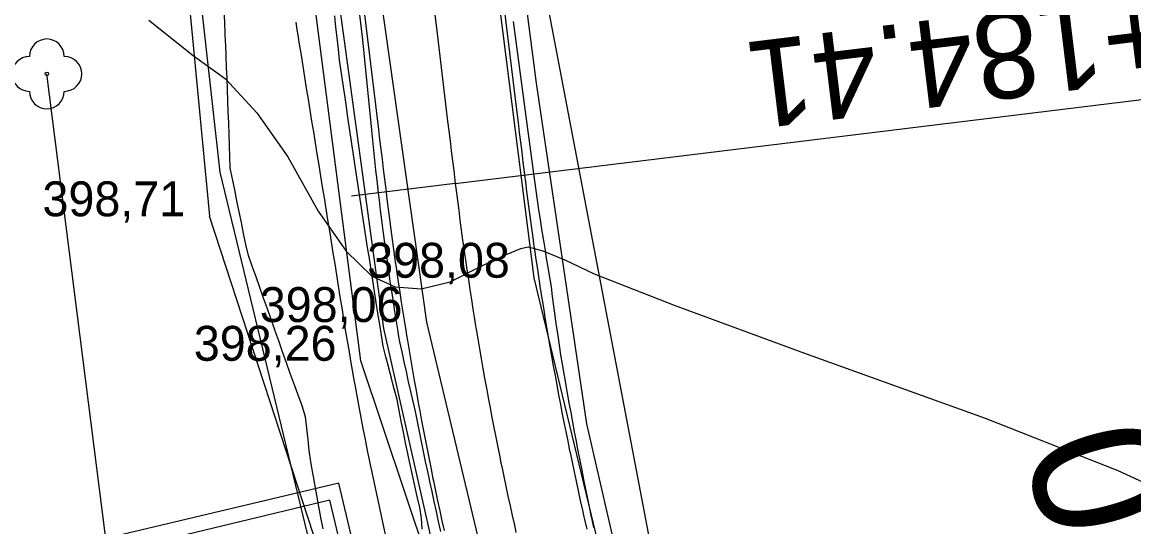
# Model space of a CAD drawing. Extents: x -574342 to -507939, y -1144044 to -1123894.
# Drawn here: x -508553.2 to -508521.32, y -1143234.06 to -1143219.6 of the extents above; entities that cross this region are included whole.
import ezdxf

# ---------------------------------------------------------------- set-up
doc = ezdxf.new("R2010")
doc.units = 0
for name, color, linetype in [('01_PARCELY_NAVRH_PC', 7, 'Continuous'), ('01_PARCELY_NAVRH_VHO', 7, 'Continuous'), ('01_PARCELY_NAVRH_ŽP', 7, 'Continuous'), ('1000', 7, 'Continuous'), ('18', 7, 'Continuous'), ('21', 7, 'Continuous'), ('23', 7, 'Continuous'), ('37', 7, 'Continuous'), ('42', 7, 'Continuous'), ('54', 7, 'Continuous'), ('55', 7, 'Continuous'), ('62', 7, 'Continuous'), ('Level 255', 7, 'Continuous'), ('SO 101_popis oblouku', 7, 'Continuous'), ('VRST VEDL', 7, 'Continuous')]:
    doc.layers.add(name, color=color, linetype=linetype)

msp = doc.modelspace()

# ---------------------------------------------------------------- linework, layer by layer
msp.add_lwpolyline([(-508538.692, -1143255.691), (-508544.119, -1143232.805), (-508565.304, -1143237.829), (-508559.878, -1143260.714)], close=True)
at = {"layer": '01_PARCELY_NAVRH_PC'}
msp.add_lwpolyline([(-508524.61, -1143277.77), (-508531.94, -1143260.32), (-508534.5, -1143254.93), (-508536.24, -1143250.83), (-508539.07, -1143243.44), (-508539.77, -1143241.25), (-508540.55, -1143238.43), (-508542.83, -1143228.38), (-508544.32, -1143217.47), (-508545.45, -1143205.07), (-508545.52, -1143198.58), (-508545.24, -1143191.32), (-508544.97, -1143188.3), (-508544.25, -1143181.83), (-508541.94, -1143173.53), (-508537.18, -1143176.51), (-508538.65, -1143182.46), (-508540.32, -1143193.28), (-508540.02, -1143209.35), (-508538.46, -1143221.35), (-508537.02, -1143231.11), (-508535.34, -1143238.37), (-508531.16, -1143250.06), (-508524.26, -1143263.08)], dxfattribs=at)
msp.add_lwpolyline([(-508524.61, -1143277.77), (-508531.94, -1143260.32), (-508534.5, -1143254.93), (-508536.24, -1143250.83), (-508539.07, -1143243.44), (-508539.77, -1143241.25), (-508540.55, -1143238.43), (-508542.83, -1143228.38), (-508544.32, -1143217.47), (-508545.45, -1143205.07), (-508545.52, -1143198.58), (-508545.24, -1143191.32), (-508544.97, -1143188.3), (-508544.25, -1143181.83), (-508541.94, -1143173.53), (-508537.18, -1143176.51), (-508538.65, -1143182.46), (-508540.32, -1143193.28), (-508540.02, -1143209.35), (-508538.46, -1143221.35), (-508537.02, -1143231.11), (-508535.34, -1143238.37), (-508531.16, -1143250.06), (-508524.26, -1143263.08)], dxfattribs=at)
at = {"layer": '01_PARCELY_NAVRH_VHO'}
msp.add_lwpolyline([(-508536.24, -1143250.83), (-508539.07, -1143243.44), (-508539.77, -1143241.25), (-508540.55, -1143238.43), (-508542.83, -1143228.38), (-508544.32, -1143217.47), (-508545.45, -1143205.07), (-508545.52, -1143198.58), (-508545.24, -1143191.32), (-508544.97, -1143188.3), (-508544.25, -1143181.83), (-508551.68, -1143170.14), (-508558.5, -1143170.32), (-508555.03, -1143173.64), (-508548.66, -1143186.8), (-508549.63, -1143198.15), (-508549.79, -1143203.71), (-508547.53, -1143223.9), (-508542.99, -1143242.68), (-508538.24, -1143253.15)], close=True, dxfattribs=at)
at = {"layer": '01_PARCELY_NAVRH_ŽP'}
msp.add_lwpolyline([(-508555.03, -1143173.64), (-508548.66, -1143186.8), (-508549.63, -1143198.15), (-508549.79, -1143203.71), (-508547.53, -1143223.9), (-508542.99, -1143242.68), (-508538.24, -1143253.15), (-508539.95, -1143255.3), (-508547.25, -1143258.62), (-508651.11, -1143191.46), (-508662.59, -1143152.85), (-508637.59, -1143153.08), (-508621.09, -1143158.13), (-508610.87, -1143164.96), (-508585.59, -1143176.01), (-508569.25, -1143175.97)], close=True, dxfattribs=at)
at = {"layer": '1000'}
for points in [[(-508540.667, -1143208.641), (-508539.328, -1143219.604), (-508539.013, -1143222.188), (-508538.978, -1143222.472), (-508538.943, -1143222.756), (-508538.908, -1143223.041), (-508538.874, -1143223.325), (-508538.839, -1143223.61), (-508538.804, -1143223.894), (-508538.794, -1143223.978), (-508538.77, -1143224.174), (-508538.735, -1143224.453), (-508538.699, -1143224.731), (-508538.662, -1143225.01), (-508538.625, -1143225.288), (-508538.587, -1143225.566), (-508538.548, -1143225.844), (-508538.533, -1143225.95), (-508538.508, -1143226.122), (-508538.467, -1143226.4), (-508538.426, -1143226.678), (-508538.384, -1143226.955), (-508538.341, -1143227.233), (-508538.297, -1143227.51), (-508538.253, -1143227.787), (-508538.231, -1143227.917), (-508538.207, -1143228.064), (-508538.161, -1143228.341), (-508538.114, -1143228.618), (-508538.066, -1143228.895), (-508538.018, -1143229.171), (-508537.969, -1143229.448), (-508537.918, -1143229.724), (-508537.89, -1143229.877), (-508537.868, -1143230), (-508537.816, -1143230.276), (-508537.763, -1143230.552), (-508537.71, -1143230.828), (-508537.656, -1143231.103), (-508537.601, -1143231.379), (-508537.546, -1143231.654), (-508537.51, -1143231.83), (-508537.489, -1143231.929), (-508537.432, -1143232.204), (-508537.374, -1143232.478), (-508537.315, -1143232.753), (-508537.256, -1143233.027), (-508537.195, -1143233.302), (-508537.134, -1143233.576), (-508537.089, -1143233.774), (-508537.072, -1143233.85), (-508537.009, -1143234.123)], [(-508544.763, -1143209.141), (-508543.435, -1143220.105), (-508543.18, -1143222.696), (-508543.152, -1143222.982), (-508543.124, -1143223.267), (-508543.096, -1143223.552), (-508543.067, -1143223.837), (-508543.033, -1143224.122), (-508543, -1143224.406), (-508542.99, -1143224.49), (-508542.965, -1143224.695), (-508542.929, -1143224.986), (-508542.892, -1143225.276), (-508542.854, -1143225.567), (-508542.816, -1143225.857), (-508542.776, -1143226.147), (-508542.735, -1143226.437), (-508542.72, -1143226.548), (-508542.694, -1143226.727), (-508542.652, -1143227.017), (-508542.609, -1143227.307), (-508542.565, -1143227.597), (-508542.52, -1143227.886), (-508542.474, -1143228.175), (-508542.428, -1143228.464), (-508542.406, -1143228.6), (-508542.376, -1143228.753), (-508542.315, -1143229.04), (-508542.254, -1143229.326), (-508542.191, -1143229.612), (-508542.128, -1143229.899), (-508542.063, -1143230.184), (-508541.998, -1143230.47), (-508541.962, -1143230.628), (-508541.932, -1143230.755), (-508541.869, -1143231.041), (-508541.812, -1143231.328), (-508541.755, -1143231.615), (-508541.697, -1143231.902), (-508541.639, -1143232.189), (-508541.579, -1143232.475), (-508541.54, -1143232.658), (-508541.518, -1143232.761), (-508541.456, -1143233.047), (-508541.394, -1143233.333), (-508541.33, -1143233.619), (-508541.266, -1143233.904), (-508541.2, -1143234.189)], [(-508544.637, -1143209.126), (-508543.299, -1143220.089), (-508542.983, -1143222.672), (-508542.948, -1143222.957), (-508542.914, -1143223.241), (-508542.879, -1143223.526), (-508542.844, -1143223.81), (-508542.809, -1143224.094), (-508542.775, -1143224.379), (-508542.764, -1143224.463), (-508542.739, -1143224.667), (-508542.703, -1143224.957), (-508542.666, -1143225.247), (-508542.627, -1143225.537), (-508542.589, -1143225.826), (-508542.549, -1143226.116), (-508542.508, -1143226.405), (-508542.492, -1143226.516), (-508542.467, -1143226.695), (-508542.425, -1143226.984), (-508542.381, -1143227.273), (-508542.338, -1143227.562), (-508542.293, -1143227.851), (-508542.247, -1143228.139), (-508542.201, -1143228.428), (-508542.179, -1143228.563), (-508542.154, -1143228.716), (-508542.106, -1143229.004), (-508542.057, -1143229.292), (-508542.007, -1143229.58), (-508541.957, -1143229.868), (-508541.905, -1143230.156), (-508541.853, -1143230.444), (-508541.824, -1143230.603), (-508541.8, -1143230.731), (-508541.746, -1143231.018), (-508541.692, -1143231.305), (-508541.636, -1143231.592), (-508541.58, -1143231.879), (-508541.523, -1143232.166), (-508541.465, -1143232.452), (-508541.428, -1143232.635), (-508541.406, -1143232.738), (-508541.347, -1143233.024), (-508541.286, -1143233.31), (-508541.225, -1143233.596), (-508541.163, -1143233.882), (-508541.1, -1143234.167)], [(-508544.57, -1143234.112), (-508544.631, -1143233.793), (-508544.691, -1143233.474), (-508544.749, -1143233.155), (-508544.807, -1143232.835), (-508544.845, -1143232.616), (-508544.863, -1143232.516), (-508544.918, -1143232.196), (-508544.966, -1143231.875), (-508545.002, -1143231.551), (-508545.036, -1143231.228), (-508545.07, -1143230.904), (-508545.167, -1143230.592), (-508545.208, -1143230.485), (-508545.283, -1143230.284), (-508545.392, -1143229.99), (-508545.398, -1143229.975), (-508545.511, -1143229.665), (-508545.623, -1143229.355), (-508545.734, -1143229.044), (-508545.843, -1143228.732), (-508545.952, -1143228.42), (-508545.953, -1143228.416), (-508546.059, -1143228.114), (-508546.167, -1143227.808), (-508546.275, -1143227.502), (-508546.384, -1143227.197), (-508546.493, -1143226.891), (-508546.602, -1143226.585), (-508546.711, -1143226.28), (-508546.786, -1143225.969), (-508546.848, -1143225.655), (-508546.911, -1143225.342), (-508546.975, -1143225.029), (-508547.039, -1143224.716), (-508547.103, -1143224.403), (-508547.167, -1143224.091), (-508547.232, -1143223.778), (-508547.246, -1143223.457), (-508547.256, -1143223.135), (-508547.266, -1143222.814), (-508547.277, -1143222.492), (-508547.289, -1143222.171), (-508547.3, -1143221.849), (-508547.312, -1143221.528), (-508547.324, -1143221.207), (-508547.336, -1143220.885), (-508547.349, -1143220.564), (-508547.362, -1143220.243), (-508547.365, -1143220.151), (-508547.375, -1143219.922), (-508547.388, -1143219.601), (-508547.402, -1143219.28)], [(-508541.727, -1143234.125), (-508541.75, -1143233.813), (-508541.8, -1143233.501), (-508541.87, -1143233.193), (-508541.939, -1143232.885), (-508542.007, -1143232.577), (-508542.074, -1143232.268), (-508542.119, -1143232.057), (-508542.139, -1143231.96), (-508542.204, -1143231.651), (-508542.267, -1143231.342), (-508542.328, -1143231.032), (-508542.389, -1143230.722), (-508542.448, -1143230.412), (-508542.528, -1143230.106), (-508542.556, -1143229.999), (-508542.609, -1143229.8), (-508542.686, -1143229.508), (-508542.689, -1143229.494), (-508542.769, -1143229.187), (-508542.844, -1143228.879), (-508542.896, -1143228.567), (-508542.946, -1143228.256), (-508542.996, -1143227.944), (-508542.996, -1143227.939), (-508543.045, -1143227.628), (-508543.095, -1143227.313), (-508543.144, -1143226.998), (-508543.194, -1143226.683), (-508543.243, -1143226.367), (-508543.292, -1143226.052), (-508543.341, -1143225.736), (-508543.389, -1143225.421), (-508543.438, -1143225.106), (-508543.486, -1143224.79), (-508543.534, -1143224.475), (-508543.582, -1143224.159), (-508543.629, -1143223.844), (-508543.677, -1143223.528), (-508543.724, -1143223.212), (-508543.771, -1143222.897), (-508543.818, -1143222.581), (-508543.865, -1143222.265), (-508543.912, -1143221.95), (-508543.958, -1143221.634), (-508544.004, -1143221.318), (-508544.05, -1143221.002), (-508544.095, -1143220.686), (-508544.13, -1143220.369), (-508544.165, -1143220.051), (-508544.2, -1143219.733), (-508544.21, -1143219.642), (-508544.235, -1143219.416)], [(-508539.124, -1143219.579), (-508538.777, -1143222.159), (-508538.739, -1143222.443), (-508538.701, -1143222.727), (-508538.663, -1143223.011), (-508538.625, -1143223.295), (-508538.587, -1143223.579), (-508538.55, -1143223.863), (-508538.538, -1143223.947), (-508538.512, -1143224.142), (-508538.474, -1143224.42), (-508538.435, -1143224.697), (-508538.393, -1143224.974), (-508538.35, -1143225.251), (-508538.306, -1143225.527), (-508538.261, -1143225.804), (-508538.243, -1143225.909), (-508538.215, -1143226.08), (-508538.169, -1143226.356), (-508538.121, -1143226.632), (-508538.073, -1143226.908), (-508538.034, -1143227.185), (-508537.998, -1143227.462), (-508537.96, -1143227.74), (-508537.942, -1143227.87), (-508537.922, -1143228.017), (-508537.883, -1143228.295), (-508537.843, -1143228.572), (-508537.802, -1143228.849), (-508537.76, -1143229.126), (-508537.713, -1143229.402), (-508537.666, -1143229.678), (-508537.639, -1143229.831), (-508537.617, -1143229.954), (-508537.569, -1143230.23), (-508537.519, -1143230.505), (-508537.469, -1143230.781), (-508537.418, -1143231.056), (-508537.366, -1143231.332), (-508537.314, -1143231.607), (-508537.28, -1143231.783), (-508537.261, -1143231.882), (-508537.208, -1143232.157), (-508537.154, -1143232.432), (-508537.099, -1143232.706), (-508537.043, -1143232.981), (-508536.987, -1143233.255), (-508536.93, -1143233.53), (-508536.888, -1143233.729), (-508536.872, -1143233.804), (-508536.814, -1143234.078)]]:
    msp.add_lwpolyline(points, dxfattribs=at)
at = {"layer": '21'}
for points in [[(-508542.652, -1143208.884), (-508541.313, -1143219.846), (-508540.998, -1143222.43), (-508540.963, -1143222.714), (-508540.928, -1143222.999), (-508540.894, -1143223.283), (-508540.859, -1143223.568), (-508540.824, -1143223.852), (-508540.789, -1143224.136), (-508540.779, -1143224.22), (-508540.754, -1143224.421), (-508540.719, -1143224.705), (-508540.682, -1143224.989), (-508540.645, -1143225.273), (-508540.607, -1143225.557), (-508540.568, -1143225.841), (-508540.528, -1143226.125), (-508540.513, -1143226.233), (-508540.487, -1143226.408), (-508540.446, -1143226.692), (-508540.404, -1143226.975), (-508540.361, -1143227.259), (-508540.317, -1143227.542), (-508540.272, -1143227.825), (-508540.227, -1143228.108), (-508540.205, -1143228.24), (-508540.18, -1143228.39), (-508540.133, -1143228.673), (-508540.085, -1143228.955), (-508540.037, -1143229.238), (-508539.987, -1143229.52), (-508539.937, -1143229.802), (-508539.886, -1143230.084), (-508539.857, -1143230.24), (-508539.834, -1143230.366), (-508539.781, -1143230.647), (-508539.728, -1143230.929), (-508539.673, -1143231.21), (-508539.618, -1143231.491), (-508539.562, -1143231.772), (-508539.505, -1143232.053), (-508539.469, -1143232.232), (-508539.448, -1143232.334), (-508539.389, -1143232.614), (-508539.33, -1143232.894), (-508539.27, -1143233.175), (-508539.209, -1143233.455), (-508539.148, -1143233.734), (-508539.085, -1143234.014), (-508539.04, -1143234.217)], [(-508542.76, -1143234.359), (-508542.828, -1143234.054), (-508542.898, -1143233.743), (-508542.966, -1143233.431), (-508543.033, -1143233.119), (-508543.1, -1143232.807), (-508543.165, -1143232.495), (-508543.209, -1143232.281), (-508543.229, -1143232.182), (-508543.293, -1143231.869), (-508543.355, -1143231.556), (-508543.416, -1143231.243), (-508543.477, -1143230.93), (-508543.536, -1143230.616), (-508543.594, -1143230.303), (-508543.614, -1143230.193), (-508543.652, -1143229.989), (-508543.705, -1143229.69), (-508543.708, -1143229.675), (-508543.763, -1143229.36), (-508543.817, -1143229.046), (-508543.871, -1143228.731), (-508543.923, -1143228.416), (-508543.974, -1143228.101), (-508543.975, -1143228.097), (-508544.025, -1143227.786), (-508544.076, -1143227.471), (-508544.127, -1143227.156), (-508544.178, -1143226.841), (-508544.228, -1143226.526), (-508544.279, -1143226.211), (-508544.33, -1143225.896), (-508544.381, -1143225.581), (-508544.431, -1143225.266), (-508544.482, -1143224.951), (-508544.533, -1143224.636), (-508544.584, -1143224.321), (-508544.635, -1143224.006), (-508544.685, -1143223.691), (-508544.736, -1143223.375), (-508544.787, -1143223.06), (-508544.838, -1143222.745), (-508544.888, -1143222.43), (-508544.939, -1143222.115), (-508544.99, -1143221.8), (-508545.041, -1143221.485), (-508545.092, -1143221.17), (-508545.142, -1143220.855), (-508545.193, -1143220.54), (-508545.244, -1143220.225), (-508545.295, -1143219.91), (-508545.309, -1143219.819), (-508545.346, -1143219.595)]]:
    msp.add_lwpolyline(points, dxfattribs=at)
at = {"layer": '23'}
for points in [[(-508540.779, -1143224.22), (-508513.978, -1143220.947)], [(-508540.779, -1143224.22), (-508543.757, -1143224.584)]]:
    msp.add_lwpolyline(points, dxfattribs=at)
at = {"layer": '37'}
for points in [[(-508544.44, -1143182.59), (-508545.29, -1143193.14), (-508544.8, -1143205.6), (-508541.6, -1143228.19), (-508538.07, -1143243), (-508531.89, -1143258.66), (-508522.3, -1143275.29), (-508518.1, -1143283.75), (-508512.73, -1143299.25), (-508510.49, -1143313.12)], [(-508544.44, -1143182.59), (-508545.29, -1143193.14), (-508544.8, -1143205.6), (-508541.6, -1143228.19), (-508538.07, -1143243), (-508531.89, -1143258.66), (-508522.3, -1143275.29), (-508518.1, -1143283.75), (-508512.73, -1143299.25), (-508510.49, -1143313.12)], [(-508507.09, -1143312.37), (-508509.64, -1143298.16), (-508515.1, -1143282.44), (-508519.8, -1143273.76), (-508526.92, -1143261.04), (-508530.09, -1143253.58), (-508534.91, -1143241.83), (-508538.52, -1143226.92), (-508541.3, -1143204.98), (-508541.88, -1143193.39), (-508540.68, -1143183.59)], [(-508507.09, -1143312.37), (-508509.64, -1143298.16), (-508515.1, -1143282.44), (-508519.8, -1143273.76), (-508526.92, -1143261.04), (-508530.09, -1143253.58), (-508534.91, -1143241.83), (-508538.52, -1143226.92), (-508541.3, -1143204.98), (-508541.88, -1143193.39), (-508540.68, -1143183.59)]]:
    msp.add_lwpolyline(points, dxfattribs=at)
at = {"layer": '42'}
msp.add_lwpolyline([(-508475.71, -1143257.35), (-508496.39, -1143258.35), (-508520.72, -1143253.86), (-508528.66, -1143251.18), (-508534.38, -1143238.75), (-508538.15, -1143218.95), (-508538.33, -1143193.52)], dxfattribs=at)
msp.add_lwpolyline([(-508475.71, -1143257.35), (-508496.39, -1143258.35), (-508520.72, -1143253.86), (-508528.66, -1143251.18), (-508534.38, -1143238.75), (-508538.15, -1143218.95), (-508538.33, -1143193.52)], dxfattribs=at)
at = {"layer": '54'}
msp.add_circle((-508552.49, -1143221.08), 0.05, dxfattribs=at)
for centre, start, end in [((-508552.49, -1143220.58), 0, 180), ((-508552.99, -1143221.08), 90, 270), ((-508551.99, -1143221.08), 270, 90), ((-508552.49, -1143221.58), 180, 0)]:
    msp.add_arc(centre, 0.5, start, end, dxfattribs=at)
at = {"layer": '55'}
msp.add_line((-508539.2, -1143251.47), (-508547.83, -1143225.16), dxfattribs=at)
msp.add_line((-508539.2, -1143251.47), (-508547.83, -1143225.16), dxfattribs=at)
for points in [[(-508550.02, -1143195.47), (-508549.77, -1143204.85), (-508547.83, -1143225.16)], [(-508550.02, -1143195.47), (-508549.77, -1143204.85), (-508547.83, -1143225.16)], [(-508546.97, -1143246.83), (-508550.58, -1143236.13), (-508552.49, -1143221.08)], [(-508546.97, -1143246.83), (-508550.58, -1143236.13), (-508552.49, -1143221.08)]]:
    msp.add_lwpolyline(points, dxfattribs=at)
at = {"layer": '62'}
msp.add_lwpolyline([(-508535.82, -1143252.17), (-508543.49, -1143229.3), (-508544.91, -1143218.28), (-508546.55, -1143206.05), (-508547.23, -1143192.43), (-508546.71, -1143185.69)], dxfattribs=at)
msp.add_lwpolyline([(-508535.82, -1143252.17), (-508543.49, -1143229.3), (-508544.91, -1143218.28), (-508546.55, -1143206.05), (-508547.23, -1143192.43), (-508546.71, -1143185.69)], dxfattribs=at)
at = {"layer": 'SO 101_popis oblouku'}
for p, q in [((-508544.379, -1143233.297), (-508560.912, -1143237.254)), ((-508539.103, -1143255.341), (-508544.379, -1143233.297))]:
    msp.add_line(p, q, dxfattribs=at)
at = {"layer": 'VRST VEDL'}
msp.add_lwpolyline([(-508549.563, -1143219.538), (-508548.295, -1143220.549), (-508547.371, -1143221.226), (-508546.466, -1143222.196), (-508545.579, -1143223.459), (-508544.71, -1143225.015), (-508543.908, -1143226.155), (-508543.172, -1143226.878), (-508542.503, -1143227.184), (-508541.754, -1143227.237), (-508540.925, -1143227.035), (-508540.016, -1143226.581), (-508539.34, -1143226.263), (-508538.897, -1143226.082), (-508538.687, -1143226.039), (-508538.266, -1143226.147), (-508537.635, -1143226.404), (-508536.793, -1143226.813), (-508534.504, -1143227.706), (-508530.77, -1143229.084), (-508525.588, -1143230.947), (-508521.778, -1143232.443), (-508519.338, -1143233.572)], dxfattribs=at)

# ---------------------------------------------------------------- texts
at = {"layer": '18'}
for s, height, rotation, p in [('TK0+184.41', 2.5, 186.9628, (-508514.342, -1143217.969)), ('0+200', 4, 285.897, (-508524.54, -1143231.773))]:
    msp.add_text(s, height=height, rotation=rotation, dxfattribs=at).set_placement(p)
at = {"layer": 'Level 255'}
for s, p in [('398,71', (-508552.615, -1143225.16)), ('398,08', (-508543.305, -1143226.92)), ('398,06', (-508546.385, -1143228.19)), ('398,26', (-508548.275, -1143229.3))]:
    msp.add_text(s, height=1, dxfattribs=at).set_placement(p)

doc.saveas('drawing.dxf')
